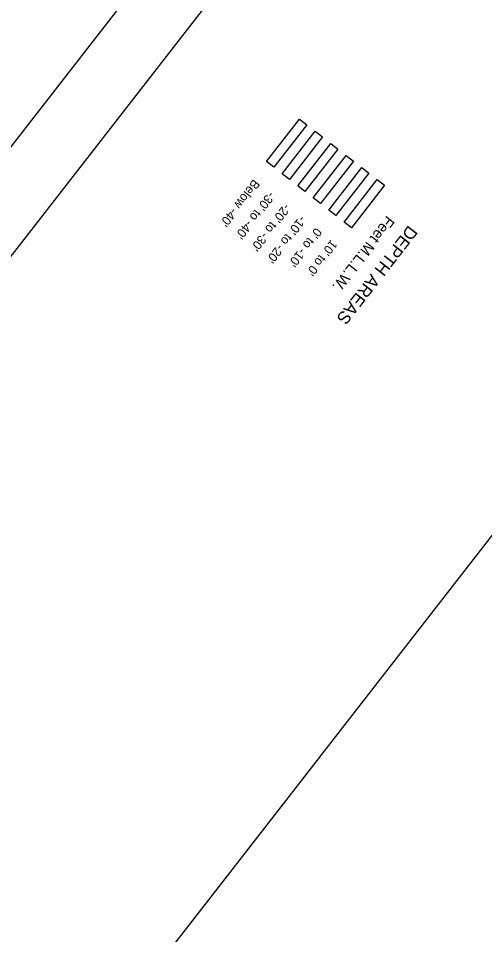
# Model space of a CAD drawing. Extents: x 3888273 to 3909528, y 158682 to 181032.
# Drawn here: x 3895725 to 3897894, y 171905 to 176166 of the extents above; entities that cross this region are included whole.
import ezdxf

# ---------------------------------------------------------------- set-up
doc = ezdxf.new("R2010")
doc.units = 0
for name, color, linetype in [('G-ANNO-NPLT', 7, 'Continuous'), ('V-ANNO-SYMB', 7, 'Continuous'), ('V-GRID-FRAM', 7, 'Continuous'), ('V-TOPO-DPTH', 7, 'Continuous')]:
    doc.layers.add(name, color=color, linetype=linetype)

msp = doc.modelspace()

# ---------------------------------------------------------------- linework, layer by layer
at = {"layer": 'G-ANNO-NPLT'}
msp.add_lwpolyline([(3899761, 180802.2), (3888502.9, 166332.7), (3898039.6, 158912.6), (3909297.7, 173382)], close=True, dxfattribs=at)
at = {"layer": 'V-ANNO-SYMB'}
msp.add_lwpolyline([(3899163.3, 179525), (3889005.4, 166469.6), (3898048.8, 159433.3), (3908206.7, 172488.7), (3899163.3, 179525)], dxfattribs=at)
at = {"layer": 'V-GRID-FRAM'}
msp.add_lwpolyline([(3907415, 172254.2), (3898317.3, 160561.5), (3891517.3, 165521.6), (3900698.9, 177323.8), (3907415, 172254.2)], dxfattribs=at)
at = {"layer": 'V-TOPO-DPTH'}
for points in [[(3897066.8, 175670.3), (3896913.3, 175473), (3896879.8, 175499.1), (3897033.3, 175696.4)], [(3897066.8, 175670.3), (3896913.3, 175473), (3896879.8, 175499.1), (3897033.3, 175696.4)], [(3897139.1, 175614.1), (3896985.6, 175416.8), (3896952, 175442.9), (3897105.5, 175640.2)], [(3897139.1, 175614.1), (3896985.6, 175416.8), (3896952, 175442.9), (3897105.5, 175640.2)], [(3897211.3, 175557.9), (3897057.8, 175360.6), (3897024.2, 175386.7), (3897177.7, 175584)], [(3897211.3, 175557.9), (3897057.8, 175360.6), (3897024.2, 175386.7), (3897177.7, 175584)], [(3897283.5, 175501.7), (3897130, 175304.4), (3897096.5, 175330.5), (3897250, 175527.8)], [(3897283.5, 175501.7), (3897130, 175304.4), (3897096.5, 175330.5), (3897250, 175527.8)], [(3897355.7, 175445.6), (3897202.2, 175248.2), (3897168.7, 175274.3), (3897322.2, 175471.7)], [(3897355.7, 175445.6), (3897202.2, 175248.2), (3897168.7, 175274.3), (3897322.2, 175471.7)], [(3897427.9, 175389.4), (3897274.4, 175192), (3897240.9, 175218.1), (3897394.4, 175415.5)], [(3897427.9, 175389.4), (3897274.4, 175192), (3897240.9, 175218.1), (3897394.4, 175415.5)]]:
    msp.add_lwpolyline(points, close=True, dxfattribs=at)

# ---------------------------------------------------------------- texts
for s, height, p in [("Below -40'", 41.5, (3896818.8, 175419.8)), ("-30' to -40'", 41.5, (3896891, 175363.6)), ("-20' to -30'", 41.5, (3896963.2, 175307.5)), ("-10' to -20'", 41.5, (3897035.4, 175251.3)), ('Feet M.L.L.W.', 50, (3897439.2, 175251.1)), ("0' to -10'", 41.5, (3897107.7, 175195.1)), ('DEPTH AREAS', 58.35, (3897540.2, 175206.6)), ("10' to 0'", 41.5, (3897179.9, 175138.9))]:
    msp.add_text(s, height=height, rotation=232.1185, dxfattribs=at).set_placement(p)

doc.saveas('drawing.dxf')
